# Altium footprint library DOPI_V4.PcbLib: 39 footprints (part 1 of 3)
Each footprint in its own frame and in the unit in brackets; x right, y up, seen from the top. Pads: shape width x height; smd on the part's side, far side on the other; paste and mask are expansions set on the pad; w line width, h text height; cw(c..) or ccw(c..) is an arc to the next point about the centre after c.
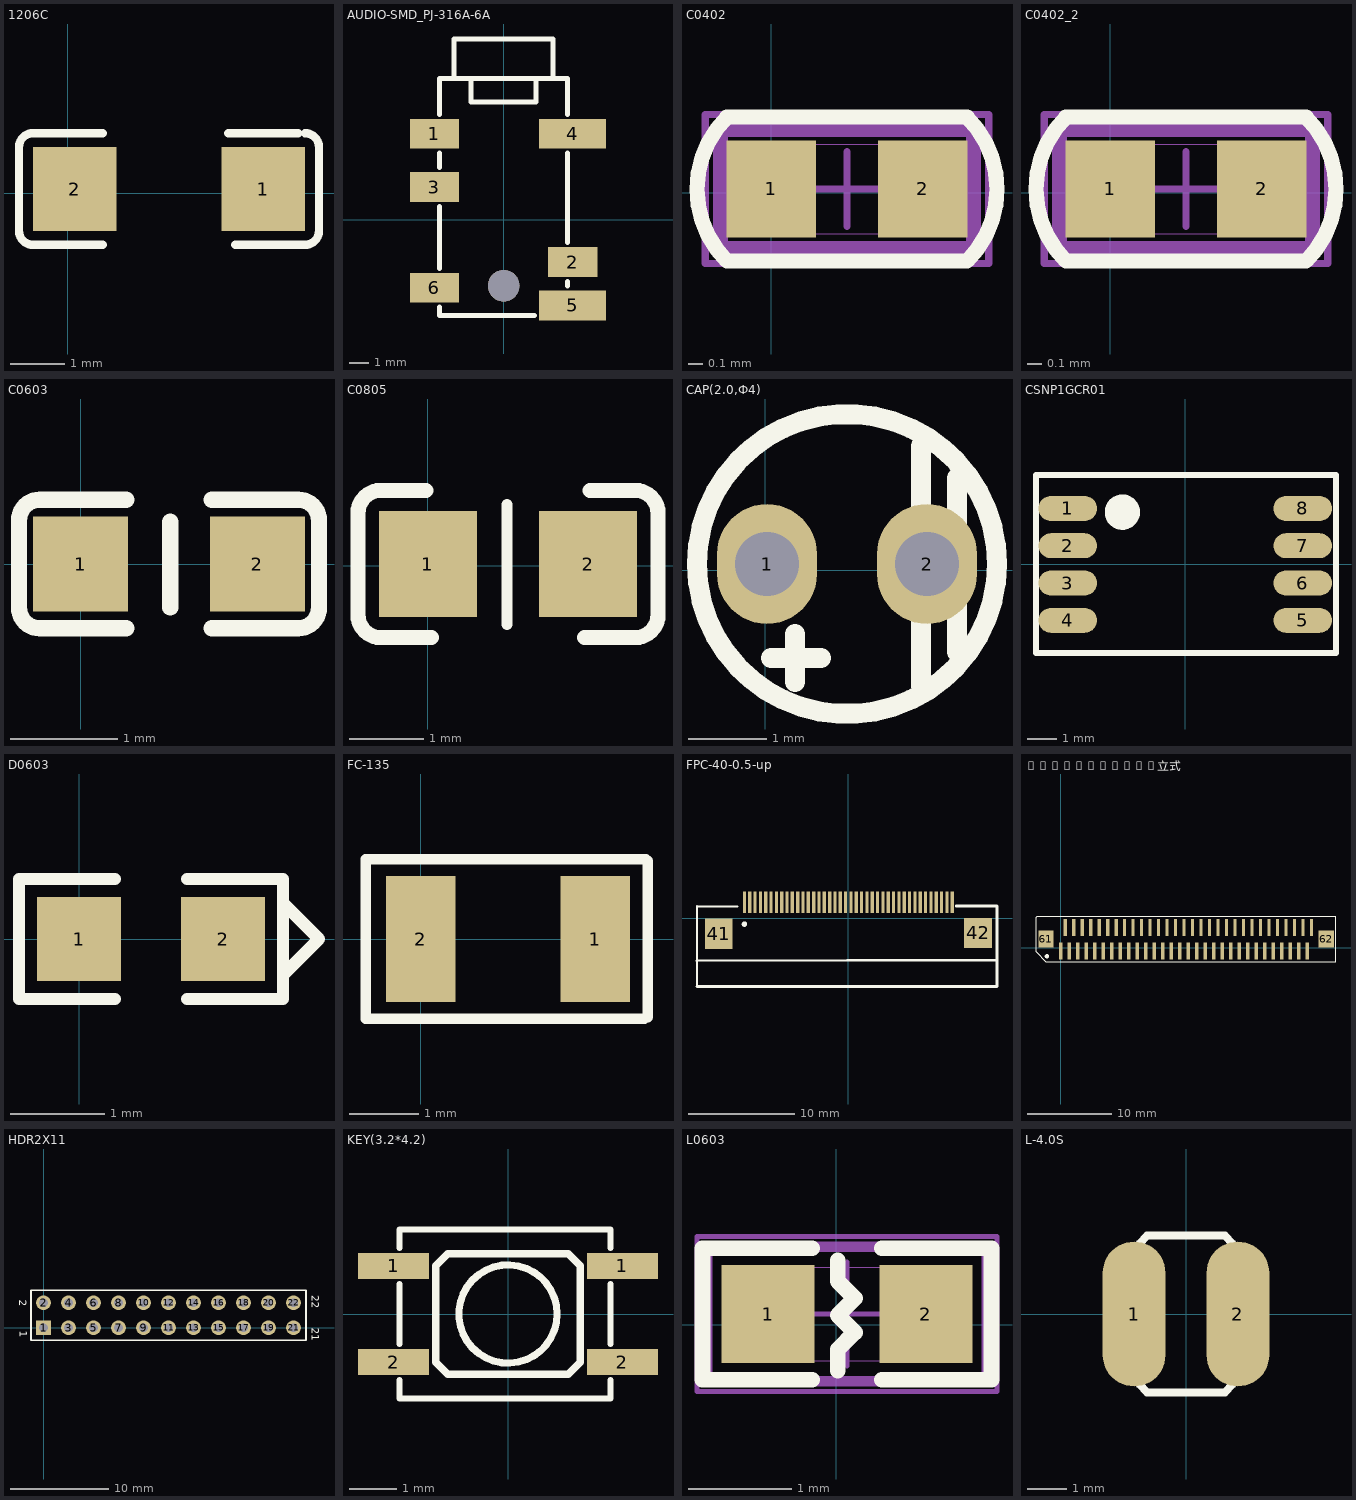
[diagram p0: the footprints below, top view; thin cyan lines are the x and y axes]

## 1206C [mil]
pads (2):
  rect 60x60 smd: 1(140,3) 2(5,3)
Top Overlay:
  lines w6: 25,-37 -25,-37 cw(c-25,-27) -35,-27 -35,33 cw(c-25,33) -25,43 25,43 ; 115,43 165,43 ; 120,-37 170,-37 ccw(c170,-27) 180,-27 180,33 ccw(c170,33) 170,43

## AUDIO-SMD_PJ-316A-6A [mm]
pads (7):
  rect 2.5x1.5 smd: 1(-3.5,4.35) 2(3.5,-2.15) 3(-3.5,1.65) 6(-3.5,-3.45)
  rect 3.4x1.5 smd: 4(3.5,4.35) 5(3.5,-4.35)
  round 1.6 hole 1.6 unplated: ""(0,-3.35)
Top Overlay:
  lines w0.254: -3.25,-4.431 -3.25,-4.85 1.569,-4.85 ; -3.25,-2.469 -3.25,0.669 ; -3.25,2.631 -3.25,3.369 ; -3.25,5.331 -3.25,7.15 3.25,7.15 3.25,5.331 ; -2.5,7.15 -2.499,8.356 -2.5,9.15 2.5,9.15 2.5,7.15 ; -1.65,7.15 -1.65,5.95 1.65,5.95 1.65,7.15 ; 3.25,-3.369 3.25,-3.131 ; 3.25,-1.169 3.25,3.369

## C0402 [mm]
pads (2):
  rect 0.6x0.65 smd: 1(0,0.025) 2(1.016,0.025)
Top Overlay:
  lines w0.102: -0.299,0.507 ccw(c0.182,0.025) -0.298,-0.457 1.314,-0.457 ccw(c0.834,0.025) 1.315,0.507 1.314,0.508 -0.298,0.508 -0.299,0.507
Mechanical 15:
  lines w0.1: -0.342,-0.375 -0.342,0.425 1.358,0.425 1.358,-0.375 -0.342,-0.375
  text "1" at 0.426,-0.2 h0.38
Mechanical 16:
  lines w0.001: -0.042,-0.275 -0.042,0.325 1.058,0.325 1.058,-0.275 -0.042,-0.275
  lines w0.05: 0.258,0.025 0.758,0.025 ; 0.508,-0.225 0.508,0.275 ; -0.442,-0.475 -0.442,0.525 1.458,0.525 1.458,-0.475 -0.442,-0.475
3D body "0402 SMD Capacitor.step": height 0.2, standoff 0, extent 0.025,-0.275 1.025,0.325

## C0402_2 [mm]
pads (2):
  rect 0.6x0.65 smd: 1(0,0.025) 2(1.016,0.025)
Top Overlay:
  lines w0.102: -0.299,0.507 ccw(c0.182,0.025) -0.298,-0.457 1.314,-0.457 ccw(c0.834,0.025) 1.315,0.507 1.314,0.508 -0.298,0.508 -0.299,0.507
Mechanical 15:
  lines w0.1: -0.342,-0.375 1.358,-0.375 1.358,0.425 -0.342,0.425 -0.342,-0.375
  text "1" at 0.426,-0.2 h0.38
Mechanical 16:
  lines w0.001: -0.042,-0.275 1.058,-0.275 1.058,0.325 -0.042,0.325 -0.042,-0.275
  lines w0.05: 0.258,0.025 0.758,0.025 ; 0.508,-0.225 0.508,0.275 ; -0.442,-0.475 1.458,-0.475 1.458,0.525 -0.442,0.525 -0.442,-0.475

## C0603 [mil]
pads (2):
  rect 35x35 smd: 1(0,0) 2(65,0)
Top Overlay:
  lines w6: 16.75,-23.62 -15,-23.62 cw(c-15,-16) -22.62,-16 -22.62,16 cw(c-15,16) -15,23.62 16.75,23.62 ; 33,-16 33,15.5 ; 48.25,-23.62 80,-23.62 ccw(c80,-16) 87.62,-16 87.62,16 ccw(c80,16) 80,23.62 48.25,23.62

## C0805 [mil]
pads (2):
  rect 52x56 smd: 1(0,1) 2(85,1)
Top Overlay:
  lines w6: 42,-31 42,32.5
  lines w8: -1,40 -25,40 ccw(c-25,28) -37,28 -37,-26 ccw(c-25,-26) -25,-38 2,-38 ; 83,-38 110,-38 ccw(c110,-26) 122,-26 122,28 ccw(c110,28) 110,40 86,40
3D body "cap_0805-1.step": height 47.24, standoff 0, extent 2,-22 80.74,25.24

## CAP(2.0,Ф4) [mil]
pads (2):
  oval 50x60 hole 32: 1(1,3) 2(81,3)
Top Overlay:
  circle w10: c41,3 r75
  lines w10: 3,-44 28,-44 ; 15,-56 15,-32 ; 78,-58 78,62 ; 96,-41 96,46

## CSNP1GCR01 [mm]
pads (8):
  oval 2x0.85 smd: 1(-4,1.905) 2(-4,0.635) 3(-4,-0.635) 4(-4,-1.905) 5(4,-1.905) 6(4,-0.635) 7(4,0.635) 8(4,1.905)
Top Overlay:
  circle w0.6: c-2.141,1.778 r0.3
  lines w0.2: -5.08,-3.023 5.131,-3.023 5.131,3.048 -5.08,3.048 -5.08,-3.023

## D0603 [mil]
pads (2):
  rect 35x35 smd: 1(0,0) 2(60,0)
Top Overlay:
  lines w5: 15,-25 -25,-25 -25,25 15,25 ; 45,-25 85,-25 85,25 45,25 ; 85,-15 100,0 85,15

## FC-135 [mm] "FC135与FC-13F封装大小相同，只是实体厚度不同"
pads (2):
  rect 1x1.8 smd: 1(2.5,0) 2(0,0)
Top Overlay:
  lines w0.152: 3.2,-1.143 -0.787,-1.143 -0.787,1.143 3.226,1.143 ; 3.251,-1.118 3.251,1.118

## FPC-40-0.5-up [mm] "CFP, 90-Leads, Body 1.4x5.1mm (max), Pitch 0.50mm, IPC Medium Density"
height 2.5
pads (42):
  rect 0.3x2 smd: 1(-9.761,1.488) 2(-9.261,1.488) 3(-8.761,1.488) 4(-8.261,1.488) 5(-7.761,1.488) 6(-7.261,1.488) 7(-6.761,1.488) 8(-6.261,1.488) 9(-5.761,1.488) 10(-5.261,1.488) 11(-4.761,1.488) 12(-4.261,1.488) 13(-3.761,1.488) 14(-3.261,1.488) 15(-2.761,1.488) 16(-2.261,1.488) 17(-1.761,1.488) 18(-1.261,1.488) 19(-0.761,1.488) 20(-0.261,1.488) 21(0.239,1.488) 22(0.739,1.488) 23(1.239,1.488) 24(1.739,1.488) 25(2.239,1.488) 26(2.739,1.488) 27(3.239,1.488) 28(3.739,1.488) 29(4.239,1.488) 30(4.739,1.488) 31(5.239,1.488) 32(5.739,1.488) 33(6.239,1.488) 34(6.739,1.488) 35(7.239,1.488) 36(7.739,1.488) 37(8.239,1.488) 38(8.739,1.488) 39(9.239,1.488) 40(9.739,1.488)
  rect 2.6x2.85 smd: 41(-12.161,-1.488) 42(12.161,-1.397)
Top Overlay:
  circle w0.25: c-9.759,-0.57 r0.125
  lines w0.2: -14.206,-6.412 -14.206,1.107 -14.18,1.081 -10.396,1.081
  lines w0.254: -14.206,-6.412 13.939,-6.412 13.939,1.081 ; -14.206,-4.001 13.938,-3.937 ; 10.129,1.143 13.939,1.143

## FPC-60-0.5-立式 [mm] "Pitch 0.50mm,"
height 2.65
pads (62):
  rect 0.4x2 smd: 1(0,-0.375) 2(0.5,2.375) 3(1,-0.375) 4(1.5,2.375) 5(2,-0.375) 6(2.5,2.375) 7(3,-0.375) 8(3.5,2.375) 9(4,-0.375) 10(4.5,2.375) 11(5,-0.375) 12(5.5,2.375) 13(6,-0.375) 14(6.5,2.375) 15(7,-0.375) 16(7.5,2.375) 17(8,-0.375) 18(8.5,2.375) 19(9,-0.375) 20(9.5,2.375) 21(10,-0.375) 22(10.5,2.375) 23(11,-0.375) 24(11.5,2.375) 25(12,-0.375) 26(12.5,2.375) 27(13,-0.375) 28(13.5,2.375) 29(14,-0.375) 30(14.5,2.375) 31(15,-0.375) 32(15.5,2.375) 33(16,-0.375) 34(16.5,2.375) 35(17,-0.375) 36(17.5,2.375) 37(18,-0.375) 38(18.5,2.375) 39(19,-0.375) 40(19.5,2.375) 41(20,-0.375) 42(20.5,2.375) 43(21,-0.375) 44(21.5,2.375) 45(22,-0.375) 46(22.5,2.375) 47(23,-0.375) 48(23.5,2.375) 49(24,-0.375) 50(24.5,2.375) 51(25,-0.375) 52(25.5,2.375) 53(26,-0.375) 54(26.5,2.375) 55(27,-0.375) 56(27.5,2.375) 57(28,-0.375) 58(28.5,2.375) 59(29,-0.375) 60(29.5,2.375)
  rect 1.8x2 smd: 61(-1.75,1) 62(31.25,1)
Top Overlay:
  circle w0.25: c-1.649,-1.016 r0.125
  lines w0.127: -2.921,-0.508 -1.778,-1.651 32.385,-1.651 32.385,3.683 -2.794,3.683 -2.826,3.651 -2.889,3.588 -2.921,3.556 -2.921,-0.508

## HDR2X11 [mm] "Connector; Header; 11x2 Position"
pads (22):
  rect 1.5x1.5 hole 0.9: 1(0,0)
  round 1.5 hole 0.9: 2(0,2.54) 3(2.54,0) 4(2.54,2.54) 5(5.08,0) 6(5.08,2.54) 7(7.62,0) 8(7.62,2.54) 9(10.16,0) 10(10.16,2.54) 11(12.7,0) 12(12.7,2.54) 13(15.24,0) 14(15.24,2.54) 15(17.78,0) 16(17.78,2.54) 17(20.32,0) 18(20.32,2.54) 19(22.86,0) 20(22.86,2.54) 21(25.4,0) 22(25.4,2.54)
Top Overlay:
  lines w0.2: -1.27,-1.27 -1.27,3.81 26.67,3.81 26.67,-1.27 -1.27,-1.27
  text "1" at -2.438,-0.305 h0.76
  text "2" at -2.489,2.87 h0.76
  text "21" at 27.229,0 h0.76
  text "22" at 27.229,3.302 h0.76

## KEY(3.2*4.2) [mm]
pads (4):
  rect 1.5x0.55 smd mask+0.076: 1(-2.413,1.016) 1(2.413,1.016) 2(-2.413,-1.016) 2(2.413,-1.016)
Top Overlay:
  circle w0.152: c0,0 r1.036
  lines w0.127: -2.286,-1.397 -2.286,-1.778 2.159,-1.778 2.159,-1.397 ; -2.286,-0.635 -2.286,0.635 ; -2.286,1.397 -2.286,1.778 -2.032,1.778 2.159,1.778 2.159,1.397 ; 2.159,-0.635 2.159,0.635
  lines w0.152: -1.524,-1.016 -1.524,1.016 -1.27,1.27 1.27,1.27 1.524,1.016 1.524,-1.016 1.27,-1.27 -1.27,-1.27 -1.524,-1.016

## L0603 [mm]
pads (2):
  rect 0.9x0.95 smd: 1(-0.66,0.102) 2(0.864,0.102)
Top Overlay:
  lines w0.152: -0.235,-0.533 -1.295,-0.533 -1.295,0.737 -0.235,0.737 ; 0.013,-0.445 0.013,-0.241 0.178,-0.076 0.013,0.089 0.178,0.254 0.013,0.419 0.013,0.622 ; 0.438,-0.533 1.499,-0.533 1.499,0.737 0.438,0.737
Mechanical 15:
  lines w0.1: -1.248,-0.548 -1.248,0.752 1.452,0.752 1.452,-0.548 -1.248,-0.548
  text "1" at -0.024,-0.243 h0.58
Mechanical 16:
  lines w0.001: -0.748,-0.348 -0.748,0.552 0.952,0.552 0.952,-0.348 -0.748,-0.348
  lines w0.05: -0.398,0.102 0.602,0.102 ; 0.102,-0.398 0.102,0.602 ; -1.348,-0.648 -1.348,0.852 1.552,0.852 1.552,-0.648 -1.348,-0.648
3D body "User Library-0603 SMD Resistor.STEP": height 0.3, standoff 0, extent -0.698,-0.298 0.902,0.502

## L-4.0S [mm]
pads (2):
  oval 1.6x3.7 smd: 1(-1.325,0) 2(1.325,0)
Top Overlay:
  lines w0.203: -1,-2 cw(c1,0) -1,2 1,2 cw(c-1,0) 1,-2 -1,-2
